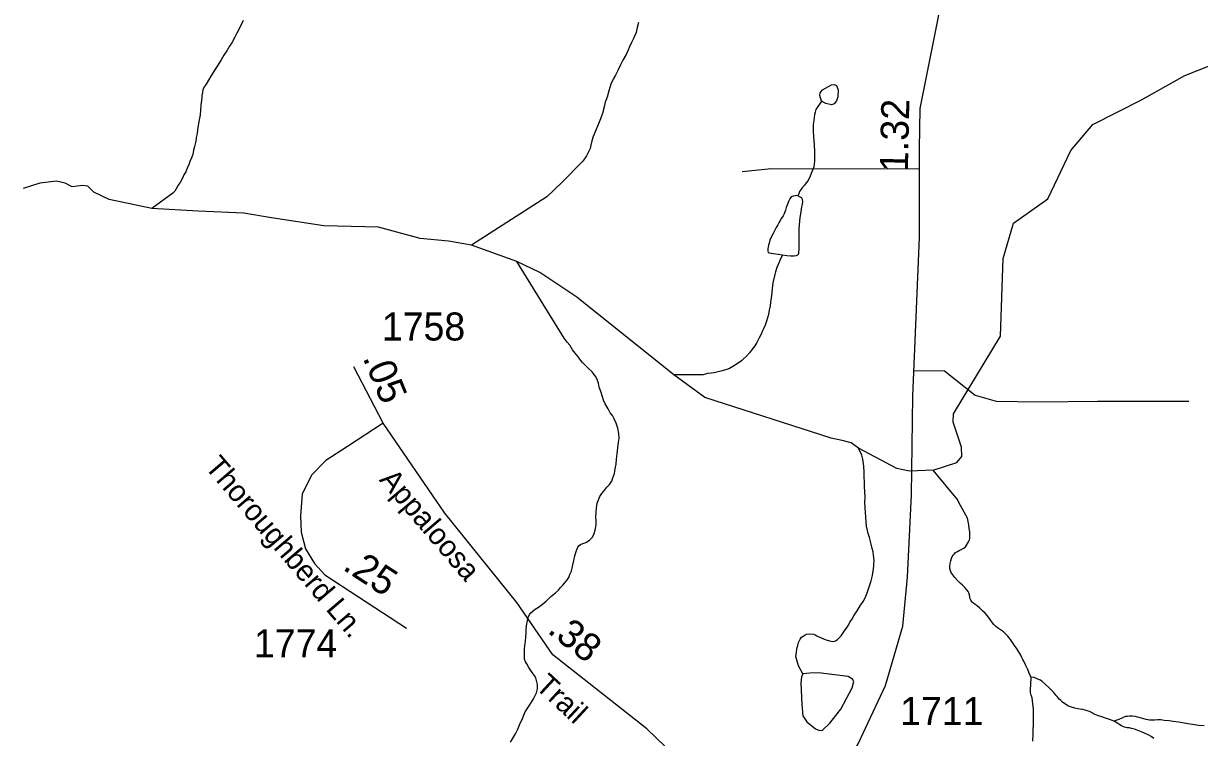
# Model space of a CAD drawing. Extents: x 2056842 to 2160602, y 826753 to 1016856.
# Drawn here: x 2125925 to 2131173, y 851982 to 855166 of the extents above; entities that cross this region are included whole.
import ezdxf

# ---------------------------------------------------------------- set-up
doc = ezdxf.new("R2010")
doc.units = 0
for name, color, linetype in [('Exist Hydrographic Creek Single Shore', 7, 'Continuous'), ('Exist Hydrographic Misc Water Feature', 7, 'Continuous'), ('Exist Road Non-System Type 51', 7, 'Continuous'), ('Exist Road Secondary Mileage Hundredths English Label', 7, 'Continuous'), ('Exist Road Secondary Type 51 Attributed', 7, 'Continuous'), ('Exist Road Secondary Type 51 Label', 7, 'Continuous'), ('Exist Road Secondary Type 51 Number Label', 7, 'Continuous')]:
    doc.layers.add(name, color=color, linetype=linetype)

msp = doc.modelspace()

# ---------------------------------------------------------------- linework, layer by layer
at = {"layer": 'Exist Hydrographic Creek Single Shore'}
for points in [[(2126905, 855179.1), (2126889.4, 855148.3), (2126876.9, 855122.6), (2126867.7, 855104.5), (2126853.7, 855080.2), (2126843.9, 855064.3), (2126832.2, 855044.5), (2126818, 855024.3), (2126806.4, 855004.2), (2126761, 854931.2), (2126749.6, 854913.5), (2126739.3, 854895.5), (2126731.3, 854883.3), (2126725.6, 854869.6), (2126723.9, 854858.9), (2126719.8, 854845.3), (2126720, 854835.5), (2126718.4, 854823.2), (2126716.3, 854803.2), (2126714.3, 854778.8), (2126712.4, 854759.2), (2126708.8, 854737), (2126704.7, 854710.9), (2126701.2, 854691.5), (2126699.5, 854675.1), (2126695.4, 854657.1), (2126693.8, 854640.7), (2126688.2, 854617.1), (2126683.9, 854600.8), (2126680, 854581.1), (2126674.3, 854566.6), (2126666.7, 854551.1), (2126662.4, 854536.3), (2126656.7, 854525), (2126648.7, 854504.7), (2126640.9, 854490.8), (2126635.1, 854478.7), (2126625.5, 854459.9), (2126615.5, 854444.8), (2126605.4, 854428.5), (2126599.9, 854417.9), (2126591.7, 854409.8), (2126497.9, 854341.4)], [(2128670.1, 855170), (2128664.1, 855147.7), (2128658.4, 855125.9), (2128648.5, 855102.3), (2128638.7, 855081.8), (2128629.1, 855061.8), (2128621.5, 855043.9), (2128613.7, 855027.6), (2128600, 855001.7), (2128589.7, 854981.3), (2128578, 854959.5), (2128566.3, 854934.9), (2128556.5, 854917.3), (2128546.4, 854895.4), (2128536.4, 854865.2), (2128529.2, 854836.7), (2128521.2, 854814.8), (2128517.5, 854800.7), (2128513.6, 854784.3), (2128509.7, 854769), (2128506, 854756.6), (2128499.9, 854740.5), (2128494.1, 854726.3), (2128486.1, 854708.5), (2128478.4, 854690.6), (2128466.5, 854662.4), (2128460.9, 854642.1), (2128457.2, 854624), (2128453.3, 854608.4), (2128443.5, 854587.9), (2128437.3, 854575.9), (2128427.7, 854562.3), (2128419.7, 854550.1), (2128327.5, 854457), (2128259.6, 854392.9), (2127924.4, 854176.8)], [(2129983.9, 853173.5), (2130089.8, 853208.7), (2130112.9, 853234.3), (2130110.5, 853276.8), (2130074, 853388.7), (2130075.2, 853425.2), (2130285.7, 853772.1), (2130296.6, 854117.2), (2130342.7, 854275.3), (2130497.1, 854383.5), (2130598.6, 854598.9), (2130697.6, 854715), (2130914.6, 854825.4), (2131107.2, 854934.4), (2131221.3, 854978.5)], [(2129983.9, 853173.5), (2129879.7, 853170.2), (2129822.3, 853180.7), (2129652.1, 853271.3), (2129618, 853296.3), (2129577.9, 853306), (2129529.3, 853317), (2128965.3, 853498.4), (2128827.2, 853598.9), (2128393.7, 853945.6), (2128229.5, 854056.2), (2128126.5, 854105.2), (2127924.4, 854176.8), (2127821.4, 854195.7), (2127694.6, 854207), (2127574, 854239.7), (2127508.7, 854257.3), (2127265.1, 854263.5), (2127031.6, 854298.7), (2126908.5, 854320.1), (2126703.8, 854328.9), (2126497.9, 854341.4), (2126307.1, 854381.6), (2126238, 854413.1), (2126211.6, 854440.7), (2126186.5, 854443.2), (2126141.3, 854436.9), (2126111.2, 854453.3), (2126072.2, 854463.3), (2125996.9, 854454.5), (2125922.8, 854430.6)], [(2130422.5, 852250.6), (2130419.4, 852254.7), (2130413.2, 852269.1), (2130406.9, 852284.6), (2130403, 852294.6), (2130397.2, 852306), (2130388.6, 852322.7), (2130384.7, 852330.2), (2130380.6, 852338.5), (2130375.9, 852348.2), (2130371.4, 852356.6), (2130364.2, 852368.2), (2130356.4, 852379.9), (2130350.7, 852388.1), (2130338.4, 852405.8), (2130330.2, 852418.4), (2130324.2, 852425.8), (2130317.9, 852434.1), (2130307.6, 852444.1), (2130297.8, 852453.3), (2130281.4, 852465.1), (2130271.7, 852471.1), (2130263.9, 852477.1), (2130255.5, 852485.3), (2130249.6, 852493.1), (2130239.1, 852507.2), (2130231.3, 852518.6), (2130225.2, 852525.6), (2130216.2, 852535.5), (2130205.1, 852547.3), (2130198.7, 852553.1), (2130193, 852558.9), (2130180.9, 852568.8), (2130172.7, 852574.9), (2130164.7, 852580.6), (2130160.2, 852584.1), (2130155.5, 852589.3), (2130152.6, 852594.2), (2130150.1, 852600.6), (2130148.5, 852608.2), (2130146.2, 852618.3), (2130143.2, 852627.3), (2130140.1, 852632.2), (2130134.4, 852640.4), (2130126.2, 852650.5), (2130115.9, 852660.6), (2130105.6, 852669.9), (2130093.8, 852682.2), (2130081.2, 852695), (2130072.6, 852706.5), (2130065.5, 852717.3), (2130061.8, 852725.6), (2130059.7, 852735.7), (2130059.1, 852745.5), (2130061.2, 852757.7), (2130062.8, 852769.7), (2130065.9, 852780.6), (2130069.8, 852789.3), (2130073.5, 852795.3), (2130078, 852799.8), (2130084.5, 852806.5), (2130092.7, 852811.8), (2130100.5, 852815.9), (2130110.2, 852819.7), (2130121.4, 852826.1), (2130128.4, 852832.4), (2130133.7, 852838.9), (2130138.5, 852846.3), (2130142.4, 852854.2), (2130146.2, 852862.6), (2130148.1, 852870.8), (2130148.5, 852878.8), (2130148.3, 852887.8), (2130147.9, 852898.8), (2130145.4, 852914.2), (2130143.6, 852930.7), (2130140.9, 852945.3), (2130137.4, 852960.4), (2130099.3, 853029.9), (2130093.3, 853042.6), (2129983.9, 853173.5)], [(2130790.5, 852054.5), (2130776, 852061.2), (2130762.6, 852065.6), (2130748.9, 852069.4), (2130736.8, 852073.6), (2130717.5, 852079.8), (2130700.9, 852087.6), (2130690.9, 852093.6), (2130682.5, 852096.9), (2130672.6, 852101.2), (2130663.2, 852103.8), (2130652.7, 852106.6), (2130640.6, 852108.4), (2130629.8, 852110.1), (2130616.6, 852112.1), (2130602.5, 852116.7), (2130588.3, 852121.7), (2130572.3, 852131.8), (2130562.5, 852139.4), (2130554.7, 852146.2), (2130547.7, 852152.9), (2130538.1, 852163.8), (2130532.2, 852171.1), (2130524, 852181.3), (2130513.7, 852191.4), (2130501.6, 852202.9), (2130484, 852219), (2130471.5, 852230.7), (2130463.5, 852236.7), (2130454, 852241), (2130445.4, 852245.5), (2130435.4, 852248.7), (2130422.5, 852250.6)], [(2130969.9, 851977.9), (2130963.4, 851982.1), (2130957.6, 851985.4), (2130947.4, 851991.4), (2130927.5, 852000.9), (2130917.4, 852004.9), (2130909.5, 852008.5), (2130895.3, 852014.3)]]:
    msp.add_lwpolyline(points, dxfattribs=at)
at = {"layer": 'Exist Hydrographic Misc Water Feature'}
for points in [[(2129485.8, 854820.1), (2129478.5, 854844.4), (2129480.3, 854856.6), (2129491.3, 854870.6), (2129530.8, 854893.1), (2129544.8, 854893.7), (2129553.3, 854888.8), (2129559.9, 854870.6), (2129558.7, 854839), (2129553.9, 854820.7), (2129542.3, 854807.3), (2129530.8, 854803.1), (2129505.3, 854809.2), (2129485.8, 854820.1)], [(2129485.8, 854820.1), (2129461, 854782.8), (2129457.3, 854770.8), (2129455.4, 854759.4), (2129453.8, 854744.6), (2129451.7, 854733.1), (2129449.7, 854715.2), (2129449.7, 854687.2), (2129449.9, 854660.8), (2129452.8, 854626.3), (2129454.8, 854592.6), (2129455, 854573.2), (2129454.8, 854554.1), (2129453, 854538.6), (2129451.5, 854527), (2129447.8, 854515), (2129443.5, 854504.3), (2129435.5, 854484.8), (2129426.1, 854466), (2129418.3, 854455), (2129409.7, 854444.5), (2129398, 854430.9), (2129392.5, 854422.4), (2129388.4, 854416.1), (2129384.7, 854406.5), (2129380.2, 854397.4)], [(2129380.2, 854397.4), (2129374.8, 854398.3), (2129368.3, 854397.6), (2129359.7, 854396.1), (2129350.4, 854392.2), (2129344.9, 854384.1), (2129339, 854372), (2129333, 854355.9), (2129329.1, 854345.9), (2129325.4, 854333.5), (2129319.3, 854317.4), (2129314.4, 854307.6), (2129307.4, 854297.3), (2129301.6, 854287.6), (2129297.3, 854279.3), (2129291.2, 854268.1), (2129284.4, 854255.7), (2129278.3, 854244.5), (2129269.9, 854229.1), (2129262.3, 854212.8), (2129256.3, 854199.1), (2129252.4, 854186.7), (2129250.2, 854177.7), (2129248.3, 854169.5), (2129246.9, 854160.8), (2129246.5, 854150.7), (2129247.7, 854144.9), (2129252, 854142.6), (2129270.3, 854139.8), (2129293.4, 854136.7), (2129312.3, 854134.7)], [(2129312.3, 854134.7), (2129331, 854131.8), (2129348.8, 854129.9), (2129362.7, 854129.4), (2129374.6, 854131.7), (2129381, 854134), (2129384.3, 854137.9), (2129385.7, 854142.2), (2129386.9, 854164.3), (2129386.3, 854189.6), (2129386.1, 854210.3), (2129386.1, 854225.7), (2129385.9, 854248.1), (2129387.6, 854268.5), (2129389.4, 854284), (2129391.2, 854300.4), (2129395.1, 854326.6), (2129398.8, 854348.7), (2129400.7, 854359.9), (2129402.7, 854372.1), (2129401.5, 854380.4), (2129398.8, 854386.5), (2129394.7, 854390.4), (2129380.2, 854397.4)], [(2128218.3, 852217.6), (2128215.7, 852229.7), (2128213.4, 852241.4), (2128207.9, 852253.7), (2128195.4, 852271.4), (2128189.4, 852281.2), (2128179.6, 852293.6), (2128171.2, 852309.5), (2128165.7, 852319.3), (2128161.3, 852331.7), (2128160.9, 852347.6), (2128160.7, 852359), (2128160.7, 852373.6), (2128162.8, 852391.5), (2128164.4, 852409.5), (2128166.5, 852431.1), (2128168.1, 852447.1), (2128167.9, 852463.7), (2128170.2, 852479.3), (2128173.6, 852503.1), (2128177.7, 852517.5), (2128183.7, 852530), (2128189.2, 852538), (2128208.9, 852554.1), (2128223.3, 852563.3), (2128240.7, 852576.1), (2128256.9, 852589.9), (2128278.6, 852610.2), (2128298.7, 852626.6), (2128312.3, 852638.7), (2128321.9, 852650.6), (2128332.2, 852660.5), (2128338.1, 852668.5), (2128348.1, 852680.7), (2128357.8, 852695.1), (2128363.5, 852709.2), (2128369.7, 852722.9), (2128375.4, 852744.8), (2128381.2, 852771.1), (2128385.3, 852791.6), (2128392.6, 852815.2), (2128398.6, 852829.8), (2128404.9, 852837.7), (2128410.7, 852841.7), (2128420.5, 852847.1), (2128434.5, 852851.9), (2128450.5, 852861.6), (2128464.4, 852875.7), (2128472.2, 852892), (2128475.9, 852906.1), (2128479.8, 852929.8), (2128479.8, 852947.7), (2128479.4, 852964), (2128481.4, 853005.9), (2128484.7, 853026.5), (2128490.7, 853041.8), (2128496.6, 853056.3), (2128506.4, 853070.2), (2128514.6, 853080.7), (2128528.2, 853098.6), (2128540.5, 853110.5), (2128550.1, 853125.3), (2128553.8, 853134.9), (2128557.9, 853147.2), (2128561.6, 853158.5), (2128565.7, 853180.6), (2128569.6, 853201.1), (2128571, 853223.2), (2128574.9, 853246.9), (2128576.8, 853273), (2128580.3, 853299.3), (2128582.5, 853317.2), (2128581.9, 853337.2), (2128577.8, 853360.9), (2128569.6, 853383.2), (2128561.4, 853402.7), (2128553.2, 853417), (2128543.6, 853430.2), (2128533.5, 853447.1), (2128521.2, 853470.1), (2128513, 853486.7), (2128508.5, 853500.8), (2128500.7, 853524.7), (2128494.1, 853544.8), (2128490.2, 853562.1), (2128486.4, 853574.4), (2128480.8, 853589), (2128469.7, 853602.4), (2128462, 853611.8), (2128446, 853627.6), (2128431.8, 853641.9), (2128421.6, 853652), (2128411.3, 853665.2), (2128401.7, 853677.7), (2128387.1, 853695.3), (2128374.8, 853711), (2128362.9, 853731), (2128350.8, 853745.1), (2128338.3, 853762.7), (2128126.5, 854105.2)], [(2129312.3, 854134.7), (2129300.8, 854109.6), (2129293.2, 854091.7), (2129287.3, 854077.1), (2129281.3, 854059), (2129277.6, 854047), (2129269.7, 854009.2), (2129266, 853984.6), (2129264.5, 853965), (2129262.1, 853943), (2129258.8, 853923.3), (2129256.9, 853906.9), (2129253, 853886.8), (2129249.4, 853868.7), (2129245.5, 853853), (2129241.4, 853839), (2129234.4, 853820.6), (2129228, 853804.9), (2129221.7, 853792.9), (2129216.3, 853780.7), (2129208.1, 853764.5), (2129198.1, 853742.6), (2129188.4, 853727.8), (2129174.5, 853708.4), (2129164.5, 853696.5), (2129150.9, 853681.9), (2129138.8, 853670), (2129129, 853662.1), (2129109.1, 853647.7), (2129091.1, 853635.8), (2129075.3, 853627.6), (2129063.4, 853623), (2129042.9, 853616.3), (2129019.7, 853610.9), (2129007.6, 853608.7), (2128993.4, 853606.3), (2128977.5, 853604.3), (2128958.8, 853599.8), (2128827.2, 853598.9)], [(2129402.9, 852265), (2129383.4, 852301.5), (2129372.4, 852342.3), (2129374.4, 852361.8), (2129376.3, 852375.8), (2129378.1, 852383.6), (2129380.2, 852391.8), (2129383.9, 852405.9), (2129390.4, 852419.5), (2129397.6, 852429.3), (2129404, 852434.1), (2129413.8, 852439.5), (2129419.5, 852441.9), (2129433.7, 852444.2), (2129449.9, 852442.1), (2129457.5, 852438.9), (2129465.5, 852434.5), (2129488.2, 852424.9), (2129507.7, 852417.1), (2129521.9, 852412.9), (2129536.2, 852410), (2129548.7, 852412.9), (2129557.7, 852419.3), (2129567.6, 852429.2), (2129573.7, 852435.5), (2129583.2, 852449.1), (2129591.6, 852461.2), (2129597.1, 852469.7), (2129606.3, 852483.4), (2129612.9, 852495.3), (2129621.1, 852508.3), (2129631, 852523.9), (2129634.6, 852531.8), (2129642.4, 852542.4), (2129650.4, 852554.6), (2129658.2, 852568.4), (2129672.2, 852588.6), (2129678.1, 852598.3), (2129683.9, 852612), (2129690, 852626.9), (2129697.6, 852648.9), (2129703.5, 852666.6), (2129707.6, 852680.6), (2129711.3, 852692.7), (2129713.4, 852704.9), (2129715.4, 852714.8), (2129717.7, 852734.3), (2129719.5, 852747.4), (2129720.4, 852759.8), (2129721, 852768.7), (2129720.1, 852784.2), (2129718.5, 852795), (2129716.3, 852809.2), (2129711.9, 852824.8), (2129707.6, 852844.5), (2129699.8, 852874.2), (2129695.1, 852891.5), (2129691.2, 852904.7), (2129687.8, 852924.2), (2129685.1, 852944.1), (2129683.7, 852965.5), (2129682.6, 852984.7), (2129680.6, 853008.1), (2129680.2, 853032.1), (2129680.4, 853052.8), (2129680, 853078.8), (2129677.5, 853100.3), (2129677.7, 853122.1), (2129677.3, 853142.1), (2129677.1, 853164), (2129675, 853191.9), (2129670.7, 853222.6), (2129666.4, 853240.7), (2129652.1, 853271.3)], [(2129402.9, 852265), (2129396.8, 852252.8), (2129394.3, 852226.1), (2129398, 852128.8), (2129402.9, 852077.7), (2129421.1, 852050.9), (2129458.8, 852020.5), (2129477, 852013.2), (2129490.4, 852014.5), (2129523.2, 852044.9), (2129571.8, 852108.1), (2129622.8, 852203), (2129630.1, 852230.9), (2129624.1, 852241.9), (2129604.6, 852254), (2129532.9, 852262.6), (2129473.3, 852269.9), (2129434.5, 852268.6), (2129402.9, 852265)], [(2128098.2, 851960.6), (2128120.3, 851998.7), (2128130.2, 852019.1), (2128139.6, 852041.2), (2128151.7, 852067), (2128163.2, 852095.7), (2128179, 852118.8), (2128192.5, 852139.1), (2128200.5, 852153.7), (2128208.5, 852169.1), (2128214.5, 852181.6), (2128219, 852198.4), (2128218.3, 852217.6)], [(2130429.4, 851965.2), (2130431.1, 851998.6), (2130430.7, 852016.9), (2130432.7, 852036.5), (2130432.5, 852058.4), (2130432.1, 852083.2), (2130432.3, 852094.6), (2130432.1, 852108.8), (2130429.6, 852132.3), (2130425.9, 852158.8), (2130421.4, 852170.5), (2130419.2, 852182.6), (2130419.6, 852196.7), (2130421.2, 852217.2), (2130422.5, 852250.6)], [(2130860.2, 852076.9), (2130852.4, 852076), (2130842.4, 852074.7), (2130830.1, 852070), (2130812.7, 852062.1), (2130790.5, 852054.5)], [(2130895.3, 852014.3), (2130883.2, 852019), (2130869.3, 852022.3), (2130861.3, 852024.4), (2130850.2, 852025.2), (2130839.3, 852028.1), (2130825, 852033.9), (2130817.2, 852038.3), (2130809.2, 852044.4), (2130796.9, 852051.9), (2130790.5, 852054.5)], [(2131194.5, 852033.1), (2131168.4, 852035), (2131142.4, 852039), (2131120.5, 852042.7), (2131098.1, 852046.5), (2131080.5, 852050), (2131056.5, 852053.6), (2131038.2, 852056), (2131016.3, 852058), (2131000.1, 852060.1), (2130986.6, 852060.2), (2130974.5, 852059.5), (2130964.2, 852059.1), (2130950.3, 852059.5), (2130935.7, 852061.3), (2130914.4, 852068.2), (2130895.9, 852072.7), (2130886.1, 852074.6), (2130874.2, 852076.3), (2130860.2, 852076.9)]]:
    msp.add_lwpolyline(points, dxfattribs=at)
at = {"layer": 'Exist Road Non-System Type 51'}
for points in [[(2129923.2, 854515.6), (2129263.1, 854517.4), (2129132.2, 854505)], [(2129898.5, 853618.7), (2130034.7, 853616.4), (2130171.8, 853508.4), (2130265.2, 853481.3), (2130454.2, 853479.3), (2130718, 853481.3), (2131125.1, 853481.3)]]:
    msp.add_lwpolyline(points, dxfattribs=at)
at = {"layer": 'Exist Road Secondary Type 51 Attributed'}
for points in [[(2129354.8, 851502.3), (2129537.9, 851761.5), (2129650.5, 851953.9), (2129771.2, 852213.4), (2129849.1, 852477.8), (2129870, 852696.4), (2129888, 853064.4), (2129893.7, 853503.6), (2129923.2, 854212), (2129923.2, 854607.5), (2129927, 854786.2), (2130002.1, 855165.6), (2130076.2, 855561.1), (2130204.4, 856143.9), (2130299.4, 856585.1), (2130361.2, 857038.6), (2130423, 857712.7), (2130464.8, 858034.1), (2130497.1, 858207.1)], [(2127530.4, 853382.8), (2127398.6, 853634.3)], [(2127530.4, 853382.8), (2127371.4, 853279.7), (2127274.1, 853217.7), (2127210, 853151.3), (2127168, 853067.3), (2127161.4, 852969.9), (2127163.6, 852896.9), (2127183.5, 852823.8), (2127223.3, 852757.4), (2127269.7, 852706.5), (2127420.1, 852609.2), (2127634.6, 852469.8)], [(2128832.2, 851900.1), (2128707.2, 852020.7), (2128287.8, 852349.9), (2128126.6, 852583.9), (2127805, 852981.7), (2127530.4, 853382.8)]]:
    msp.add_lwpolyline(points, dxfattribs=at)

# ---------------------------------------------------------------- texts
at = {"layer": 'Exist Road Secondary Mileage Hundredths English Label'}
for s, rotation, p in [('1.32', 88.7821, (2129871.7, 854502.7)), ('.05', 292.4181, (2127437.4, 853675.3)), ('.25', 326.9773, (2127344.3, 852733)), ('.38', 321.8726, (2128258.3, 852452.5))]:
    msp.add_text(s, height=125, rotation=rotation, dxfattribs=at).set_placement(p)
at = {"layer": 'Exist Road Secondary Type 51 Label'}
for s, rotation, p in [('Thoroughberd Ln.', 310.421, (2126730.2, 853187.1)), ('Appaloosa', 310.421, (2127509.4, 853129.3)), ('Trail', 317.1896, (2128204.2, 852204.6))]:
    msp.add_text(s, height=95, rotation=rotation, dxfattribs=at).set_placement(p)
at = {"layer": 'Exist Road Secondary Type 51 Number Label'}
for s, p in [('1758', (2127524.1, 853752.1)), ('1774', (2126953.1, 852339.2)), ('1711', (2129837.3, 852037))]:
    msp.add_text(s, height=125, dxfattribs=at).set_placement(p)

doc.saveas('drawing.dxf')
